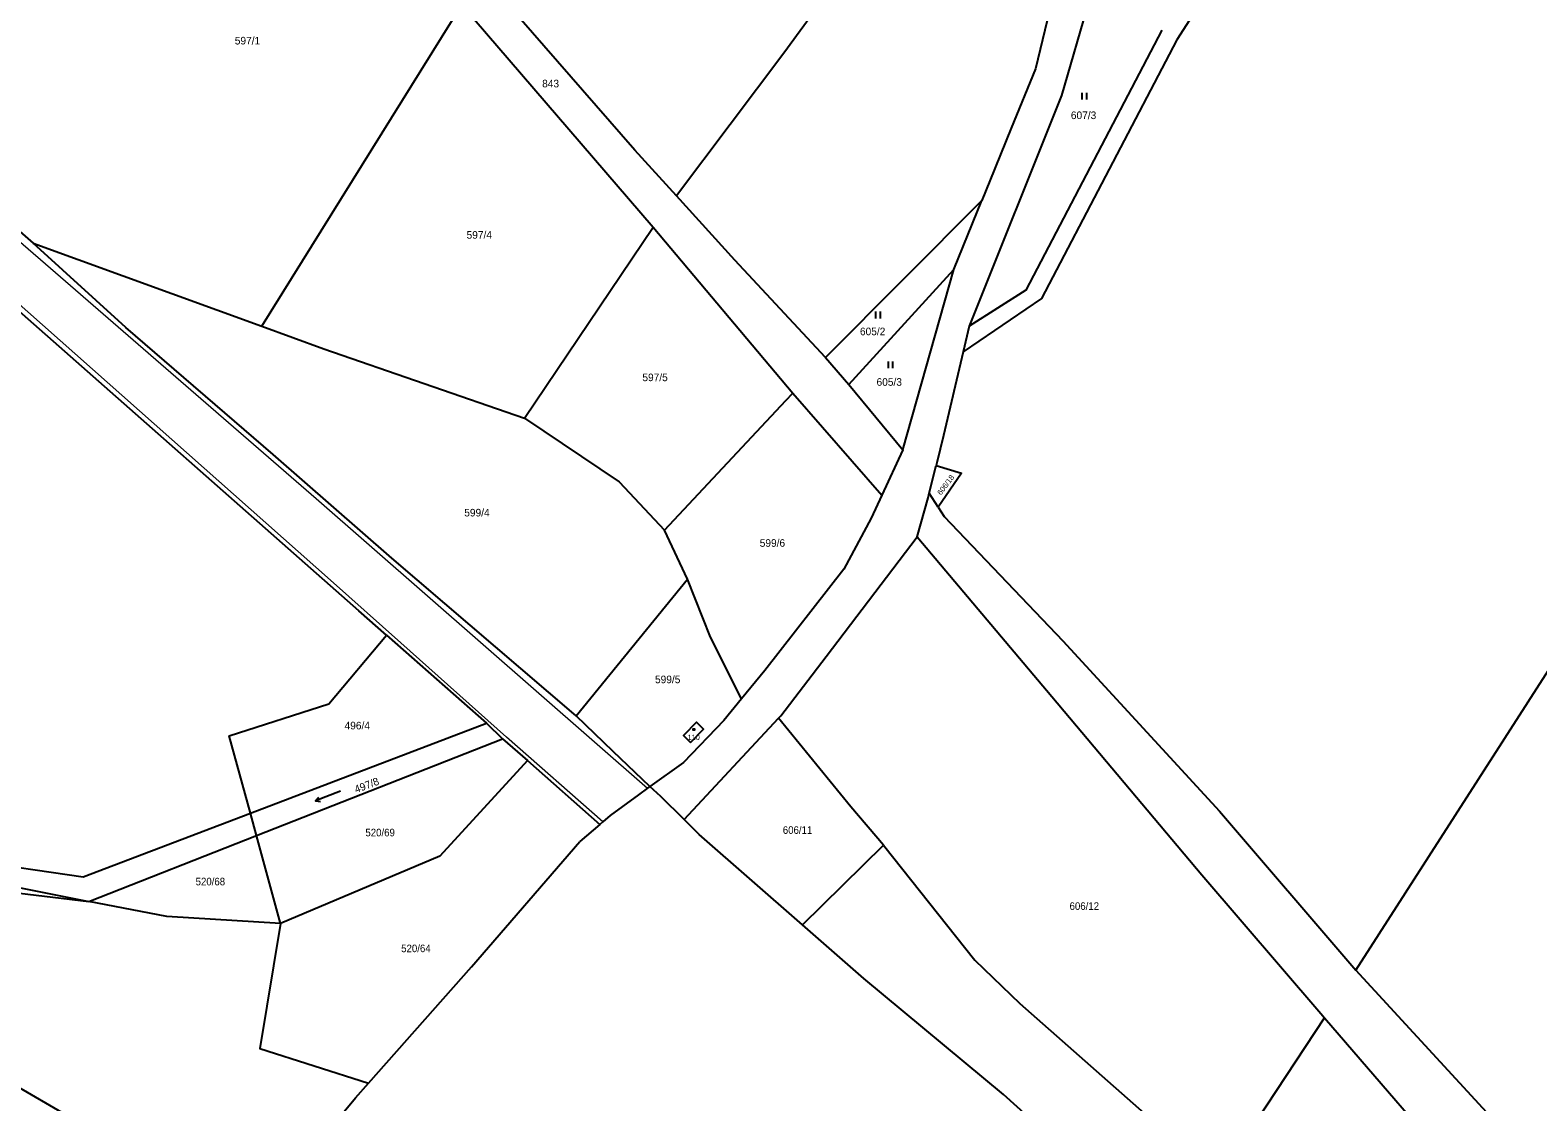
# Model space of a CAD drawing. Extents: x -687135 to -684370, y -1007309 to -1005782.
# Drawn here: x -684920.8 to -684583, y -1006790.2 to -1006550 of the extents above; entities that cross this region are included whole.
import ezdxf

# ---------------------------------------------------------------- set-up
doc = ezdxf.new("R2010")
doc.units = 0
doc.header["$LTSCALE"] = 0.68
for name, color, linetype, lineweight in [('1', 7, 'Continuous', 25), ('3', 7, 'Continuous', 25), ('4', 7, 'Continuous', 13), ('5', 7, 'Continuous', 25)]:
    doc.layers.add(name, color=color, linetype=linetype, lineweight=lineweight)
doc.layers.add('2', color=7, linetype='Continuous')

msp = doc.modelspace()

# ---------------------------------------------------------------- linework, layer by layer
at = {"layer": '1'}
for p, q in [((-684810.06, -1006636.98), (-684781.26, -1006594.14)), ((-684749.97, -1006631.36), (-684729.98, -1006654.2)), ((-684725.3, -1006644.05), (-684729.98, -1006654.2)), ((-684719.37, -1006653.81), (-684717.81, -1006647.54)), ((-684717.38, -1006656.9), (-684719.37, -1006653.81)), ((-684871.46, -1006725.48), (-684818.58, -1006705.34)), ((-684774.3, -1006726.9), (-684753.15, -1006704.21)), ((-684870.1, -1006730.49), (-684814.95, -1006708.81)), ((-684793.21, -1006727.99), (-684797.68, -1006731.81)), ((-684864.73, -1006750.17), (-684870.1, -1006730.49)), ((-684821.95, -1006759.89), (-684797.68, -1006731.81)), ((-684747.79, -1006750.47), (-684729.64, -1006732.63)), ((-684845, -1006785.98), (-684821.95, -1006759.89))]:
    msp.add_line(p, q, dxfattribs=at)
for points in [[(-684392.01, -1006333.79), (-684453.16, -1006366.8), (-684475.35, -1006380.5), (-684497.75, -1006397.56), (-684521.48, -1006427.89), (-684532.78, -1006440.46), (-684543.61, -1006452.11), (-684557.02, -1006462.61), (-684581.63, -1006475.92), (-684599.9, -1006483.3), (-684633.2, -1006496.66), (-684644.34, -1006521.69), (-684663.91, -1006552.17), (-684694.22, -1006610.15), (-684711.78, -1006622.12)], [(-684623.79, -1006760.63), (-684562.99, -1006665.84), (-684502.57, -1006571.62), (-684433.64, -1006464.64), (-684396.39, -1006406.98), (-684369.61, -1006368.79)], [(-684657.89, -1006425.71), (-684670.89, -1006440.21), (-684684.04, -1006458.84), (-684711.02, -1006499.06), (-684729.99, -1006525.08), (-684751.95, -1006555.18), (-684776.01, -1006587.17)], [(-684657.89, -1006425.71), (-684669.24, -1006457.85), (-684678.91, -1006503.04), (-684689.78, -1006534.46), (-684695.59, -1006558.66), (-684701.01, -1006571.99), (-684705.84, -1006583.77), (-684707.61, -1006588.16)], [(-685010.09, -1006519.79), (-684993.05, -1006534.8), (-684954.59, -1006567.81), (-684941.96, -1006578.76), (-684935.76, -1006584.14), (-684920.1, -1006597.74), (-684868.88, -1006616.37), (-684824.1, -1006544.38)], [(-684776.01, -1006587.17), (-684785.34, -1006576.89), (-684819.96, -1006537.11)], [(-684824.1, -1006544.38), (-684781.26, -1006594.14), (-684749.97, -1006631.36)], [(-684683.56, -1006543.2), (-684689.74, -1006564.65), (-684710.44, -1006616.37)], [(-684841, -1006685.58), (-684847.2, -1006680.11), (-684925.08, -1006611.45), (-684996.13, -1006550.77)], [(-684667.28, -1006550.01), (-684697.76, -1006608.3), (-684710.44, -1006616.37), (-684711.78, -1006622.12)], [(-684742.65, -1006623.35), (-684762.97, -1006601.54), (-684776.01, -1006587.17)], [(-684798.51, -1006703.66), (-684799.03, -1006703.24), (-684839.81, -1006668.37), (-684866.36, -1006645.1), (-684899.39, -1006616.69), (-684920.1, -1006597.74)], [(-684737.4, -1006629.4), (-684725.3, -1006644.05), (-684713.9, -1006603.63)], [(-684868.88, -1006616.37), (-684855.01, -1006621.41), (-684810.06, -1006636.98)], [(-684711.78, -1006622.12), (-684716.16, -1006640.87), (-684717.68, -1006647), (-684717.81, -1006647.54)], [(-684778.72, -1006662.06), (-684751.54, -1006633.03), (-684749.97, -1006631.36)], [(-684810.06, -1006636.98), (-684788.87, -1006651.25), (-684778.72, -1006662.06)], [(-684717.81, -1006647.54), (-684712.14, -1006649.26), (-684717.38, -1006656.9)], [(-684729.98, -1006654.2), (-684732.38, -1006659.39), (-684738.51, -1006670.83), (-684756.2, -1006693.48), (-684761.44, -1006699.87)], [(-684722.11, -1006663.56), (-684719.62, -1006654.8), (-684719.37, -1006653.81)], [(-684717.38, -1006656.9), (-684716.01, -1006659.03), (-684689.45, -1006686.84), (-684654.4, -1006725.05), (-684623.79, -1006760.63)], [(-684798.51, -1006703.66), (-684773.57, -1006673.06), (-684778.72, -1006662.06)], [(-684753.15, -1006704.21), (-684752.65, -1006703.67), (-684742.45, -1006690.36), (-684722.11, -1006663.56)], [(-684722.11, -1006663.56), (-684691.89, -1006699.34), (-684658.34, -1006739.33), (-684631.7, -1006770.35), (-684630.84, -1006771.34)], [(-684761.44, -1006699.87), (-684768.42, -1006686.05), (-684773.57, -1006673.06)], [(-684871.46, -1006725.48), (-684876.2, -1006708.12), (-684853.91, -1006700.99), (-684841, -1006685.58)], [(-684841, -1006685.58), (-684818.58, -1006705.34), (-684814.95, -1006708.81), (-684809.42, -1006713.69), (-684793.21, -1006727.99)], [(-684761.44, -1006699.87), (-684765.39, -1006704.68), (-684774.46, -1006714.09), (-684781.97, -1006719.5)], [(-684781.97, -1006719.5), (-684790.18, -1006711.67), (-684798.51, -1006703.66)], [(-684729.64, -1006732.63), (-684736.93, -1006724.05), (-684753.15, -1006704.21)], [(-685009.5, -1006714.05), (-684959.69, -1006727.98), (-684934.64, -1006735.98), (-684908.91, -1006739.74), (-684871.46, -1006725.48)], [(-685009.5, -1006714.05), (-684985.7, -1006724.97), (-684939.07, -1006739.01), (-684907.65, -1006745.25)], [(-684809.42, -1006713.69), (-684829, -1006735.15), (-684864.73, -1006750.17)], [(-685010.85, -1006719.1), (-684957.75, -1006734.19), (-684937.52, -1006741.72), (-684907.65, -1006745.25)], [(-684781.97, -1006719.5), (-684782.53, -1006719.91), (-684784.49, -1006721.34), (-684790.87, -1006726), (-684792.54, -1006727.42), (-684793.21, -1006727.99)], [(-684774.3, -1006726.9), (-684779.53, -1006721.72), (-684781.97, -1006719.5)], [(-684907.65, -1006745.25), (-684870.1, -1006730.49), (-684871.46, -1006725.48)], [(-684747.79, -1006750.47), (-684770.89, -1006730.29), (-684774.3, -1006726.9)], [(-684881.02, -1006828.49), (-684888.86, -1006809.5), (-684895.88, -1006802.9), (-684941.13, -1006776.61), (-684969.61, -1006752.46), (-685013.02, -1006728.33)], [(-684729.64, -1006732.63), (-684709.15, -1006758.42), (-684699.12, -1006768.13), (-684671.23, -1006792.68), (-684653.71, -1006806.08), (-684652.32, -1006803.97), (-684630.84, -1006771.34)], [(-684864.73, -1006750.17), (-684890.2, -1006748.62), (-684907.65, -1006745.25)], [(-684864.73, -1006750.17), (-684869.32, -1006778.19), (-684845, -1006785.98)], [(-684665.77, -1006821.93), (-684702.72, -1006788.51), (-684734.02, -1006762.5), (-684747.79, -1006750.47)], [(-684521.86, -1006875.55), (-684570.38, -1006818.76), (-684623.79, -1006760.63)], [(-684630.84, -1006771.34), (-684597.47, -1006810.06), (-684578.67, -1006832.29), (-684529.28, -1006891.13)], [(-684890.09, -1006842.2), (-684885.68, -1006836.43), (-684884, -1006833.57), (-684881.02, -1006828.49), (-684878.28, -1006823.83), (-684871.2, -1006817.36), (-684847.88, -1006789.23), (-684845, -1006785.98)]]:
    msp.add_lwpolyline(points, dxfattribs=at)
for points in [[(-684713.9, -1006603.63), (-684707.61, -1006588.16), (-684742.65, -1006623.35), (-684737.4, -1006629.4)], [(-684772.9, -1006709.64), (-684769.97, -1006706.63), (-684771.55, -1006705.09), (-684774.47, -1006708.11)]]:
    msp.add_lwpolyline(points, close=True, dxfattribs=at)
at = {"layer": '3'}
for p, q in [((-684685.101, -1006565.54), (-684685.101, -1006564.04)), ((-684684.1, -1006565.54), (-684684.1, -1006564.04)), ((-684731.321, -1006614.6), (-684731.321, -1006613.1)), ((-684730.32, -1006614.6), (-684730.32, -1006613.1)), ((-684728.531, -1006625.77), (-684728.531, -1006624.27)), ((-684727.53, -1006625.77), (-684727.53, -1006624.27)), ((-684856.84, -1006722.723), (-684856.107, -1006721.905))]:
    msp.add_line(p, q, dxfattribs=at)
msp.add_lwpolyline([(-684851.238, -1006720.573), (-684856.84, -1006722.723), (-684855.748, -1006722.841)], dxfattribs=at)
at = {"layer": '4'}
msp.add_line((-684792.54, -1006727.42), (-684814.07, -1006708.45), dxfattribs=at)
for points in [[(-685065.37, -1006416.52), (-685042.68, -1006466.37), (-685032.4, -1006488.74), (-685022.44, -1006509.59), (-684967.45, -1006559.07), (-684916.25, -1006603.35), (-684856.74, -1006654.98), (-684782.53, -1006719.91)], [(-684814.07, -1006708.45), (-684837.78, -1006687.33), (-684853.52, -1006673.26), (-684928.63, -1006606.71), (-684994.58, -1006550.04)]]:
    msp.add_lwpolyline(points, dxfattribs=at)
at = {"layer": '5'}
msp.add_circle((-684772.1268, -1006706.7192), 0.175, dxfattribs=at)

# ---------------------------------------------------------------- texts
at = {"layer": '2'}
for s, height, p in [('597/1', 1.7, (-684874.96, -1006553.23)), ('843', 1.7, (-684806.1, -1006562.84)), ('607/3', 1.7, (-684687.66, -1006569.95)), ('597/4', 1.7, (-684823.03, -1006596.76)), ('605/2', 1.7, (-684734.91, -1006618.39)), ('597/5', 1.7, (-684783.65, -1006628.679)), ('605/3', 1.7, (-684731.19, -1006629.71)), ('599/4', 1.7, (-684823.55, -1006658.99)), ('599/6', 1.7, (-684757.36, -1006665.789)), ('599/5', 1.7, (-684780.82, -1006696.36)), ('496/4', 1.7, (-684850.36, -1006706.7)), ('110', 1.19, (-684773.52, -1006709.085))]:
    msp.add_text(s, height=height, dxfattribs=at).set_placement(p)
at = {"layer": '2', "width": 1.05}
msp.add_text('606/18', height=1.19, rotation=53, dxfattribs=at).set_placement((-684716.764, -1006654.318))
at = {"layer": '2'}
msp.add_text('497/8', height=1.7, rotation=21, dxfattribs=at).set_placement((-684847.765, -1006721.033))
at = {"layer": '2', "width": 0.95}
for s, p in [('520/69', (-684845.7, -1006730.669)), ('606/11', (-684752.19, -1006730.11)), ('520/68', (-684883.73, -1006741.65)), ('606/12', (-684687.95, -1006747.15)), ('520/64', (-684837.68, -1006756.63))]:
    msp.add_text(s, height=1.7, dxfattribs=at).set_placement(p)

doc.saveas('drawing.dxf')
